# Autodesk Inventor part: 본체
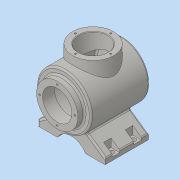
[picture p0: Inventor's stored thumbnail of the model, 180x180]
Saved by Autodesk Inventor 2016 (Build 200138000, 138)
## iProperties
Created: 2021-04
Part Number: 본체
Material: Generic
Document SubType Name: Modeling
Designer: User
Density: 1 g/cm^3
Appearance: Default
Author: User
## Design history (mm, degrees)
sketch "스케치1"
  geometry: C1 r 50 at (0, 0)
  constraints: 1 centre point
  dimensions: "d2" = 100 diameter of C1
extrude "돌출1" new body sketch "스케치1" distance "d3" = 108; taper "d4" = 0 deg
node "작업 평면1"
sketch "스케치3"
  geometry: L1 (-62, -77)-(62, -77); L2 (-62, -77)-(-62, -67); L3 (-62, -67)-(-26.694, -42.278); L4 (62, -77)-(62, -67); L5 (62, -67)-(26.694, -42.278); L6 (-26.694, -42.278)-(26.694, -42.278); A1 r 50 centre (0, 0) between (26.694, -42.278) and (-26.694, -42.278) reference; 2 further points
  constraints: 12 end point, 2 point on circle, 2 vertical, 1 horizontal, 1 midpoint, 1 vertical alignment
  dimensions: "d5" = 124 distance of L1.start L1.end; "d8" = 77 distance from line of L1 point (0, 0); "d60" = 55 deg angle of L3 L2; "d61" = 10 distance of L1.start L2.end; "d62" = 55 deg angle of L5 L4; "d63" = 10 distance of L1.end L4.end
extrude "돌출2" join sketch "스케치3" stored distance "d9" = 80; taper "d10" = 0 deg
sketch "스케치4" dims "d12" = 30
  geometry: L1 (-62, -77)-(62, -77) reference; 4 further points
  constraints: 2 vertical alignment, 1 midpoint, 2 other
  dimensions: "d13" = 15 distance from line of L1 point (0, -62)
extrude "돌출3" cut sketch "스케치4" distance "d14" = 80; taper "d15" = 0 deg
node "작업 평면2"
sketch "스케치5"
  geometry: L1 (12, -14)-(112, -14) reference; L2 (12, 94)-(112, 94) reference; L3 (112, 94)-(112, -14) reference; L4 (12, 94)-(12, -14) reference; C1 r 38 at (62, 40); 3 further points
  constraints: 2 midpoint, 1 centre point, 1 horizontal alignment, 1 vertical alignment
  dimensions: "d17" = 76 diameter of C1
extrude "돌출4" join sketch "스케치5" stored distance "d18" = 80; taper "d19" = 0 deg
sketch "스케치9"
  geometry: 1 further point
sketch "스케치11"
  geometry: C1 r 27 at (0, 0); 1 further point
  constraints: 1 centre point
  dimensions: "d25" = 54 diameter of C1
extrude "돌출5" cut sketch "스케치11" distance "d26" = 47.5; taper "d27" = 0 deg
sketch "스케치12" dims "d28" = 65
  geometry: 3 further points
  constraints: 1 horizontal alignment, 2 other
hole "구멍1" sketch "스케치12" at (-32.5, 0) diameter "d29" = 3.242; stored, may be unused: countersink angle "d33" = 90 deg, drill point angle "d35" = 118 deg; dims "d30" = 8, "d31" = 4, "d32" = 2, "d34" = 11.8
node "작업 평면3"
sketch "스케치14"
  geometry: C1 r 38 at (0, 0); 1 further point
  constraints: 1 centre point, 1 coincident
  dimensions: "d41" = 76 diameter of C1
extrude "돌출6" join sketch "스케치14" stored distance "d42" = 47.5; taper "d43" = 0 deg
sketch "스케치15"
  geometry: L1 (-38, 12)-(38, 12) reference; L2 (-50, -108)-(50, -108) reference; L3 (0, 12)-(0, -108); L4 (27, 12)-(27, -10); L5 (27, -10)-(40, -10); L6 (40, -10)-(40, -98); L7 (40, -98)-(0, -98); L8 (27, 12)-(0, 12); 1 further point
  constraints: 12 end point, 3 perpendicular, 2 midpoint, 2 point on line, 1 collinear, 1 vertical
  dimensions: "d44" = 54 diameter of L4 L3; "d45" = 80 diameter of L6 L3; "d46" = 22 distance of L4.start L4.end; "d47" = 10 distance from line of L2 L6.end
revolve "회전2" sketch "스케치15" stored, may be unused: angle "d48" = 90 deg
sketch "스케치16" dims "d49" = 65
  geometry: 3 further points
  constraints: 1 coincident, 1 vertical alignment, 2 other
hole "구멍2" sketch "스케치16" at (0, 32.5) diameter "d50" = 3.242; stored, may be unused: countersink angle "d54" = 90 deg, drill point angle "d56" = 118 deg; dims "d51" = 8, "d52" = 4, "d53" = 2, "d55" = 10
sketch "스케치17" dims "d44" = 54
  geometry: L1 (0, 80)-(36.019, 80) reference; L2 (0, 80)-(0, 0) reference; C1 r 4.5 at (8, 60); 2 further points
  constraints: 1 centre point, 1 coincident
  dimensions: "d64" = 8 distance from line of L2 point (8, 60); "d65" = 20 distance from line of L1 point (8, 60); "d66" = 9 diameter of C1
extrude "돌출7" cut sketch "스케치17" distance "d67" = 47.5; taper "d68" = 0 deg
node "작업 평면4"
sketch "스케치18"
  geometry: L1 (-8, 53)-(0, 53); L2 (0, 0)-(0, 80) reference; L3 (-8, 67)-(0, 67); L4 (0, 53)-(0, 67); C1 r 4.5 at (-8, 60) reference; A1 r 7 centre (-8, 60) between (-8, 67) and (-8, 53); 1 further point
  constraints: 6 end point, 2 horizontal, 2 point on circle, 2 point on line, 1 centre point, 1 coincident, 1 collinear, 1 tangent
  dimensions: "d70" = 14 diameter of A1
extrude "돌출8" cut sketch "스케치18" distance "d71" = 19; taper "d72" = 0 deg
fillet "모깎기1" dims "d79" = 3
chamfer "모따기1" distance "d80" = 1; stored, may be unused: second distance "d81" = 2, angle "d82" = 45 deg
fillet "모깎기2" dims "d83" = 3
fillet "모깎기4" dims "d85" = 3
fillet "모깎기5" dims "d86" = 3
node "작업 평면5"
sketch "스케치19"
  geometry: L1 (8, 67)-(16, 67) reference; L2 (16, 53)-(8, 53) reference; L3 (0, 0)-(0, 80) reference; L4 (8, 67)-(16, 67) reference; L5 (8, 67)-(0, 67); L6 (0, 0)-(0, 80) reference; L7 (16, 53)-(8, 53) reference; L8 (0, 53)-(8, 53); L9 (8, 53)-(8, 67); L10 (0, 67)-(0, 53); 1 further point
  constraints: 8 end point, 3 point on line, 2 collinear, 1 perpendicular
extrude "돌출9" cut sketch "스케치19" distance "d89" = 19; taper "d90" = 0 deg
fillet "모깎기7" dims "d94" = 3
fillet "모깎기8" dims "d101" = 3
sketch "스케치25"
  geometry: C1 r 50 at (0, 0) reference; A1 r 47 centre (0, 0) between (0, 47) and (47, 0) reference; 3 further points
  constraints: 2 horizontal alignment, 2 point on circle, 1 coincident, 1 vertical alignment, 2 other
feature "엠보싱1" sketch "스케치25" dims "d102" = 0.5, "d103" = 0
fillet "모깎기9" dims "d104" = 3
node "솔리드1"
pattern_circular "원형 패턴1" dims angle "d37" = 360 deg
pattern_circular "원형 패턴2" dims angle "d58" = 360 deg
pattern_linear "직사각형 패턴1" dims "d78" = 108
pattern_linear "직사각형 패턴2" dims "d93" = 40
other parameters: "d16" = -142, "d40" = 12, "d69" = -25, "d88" = -25
